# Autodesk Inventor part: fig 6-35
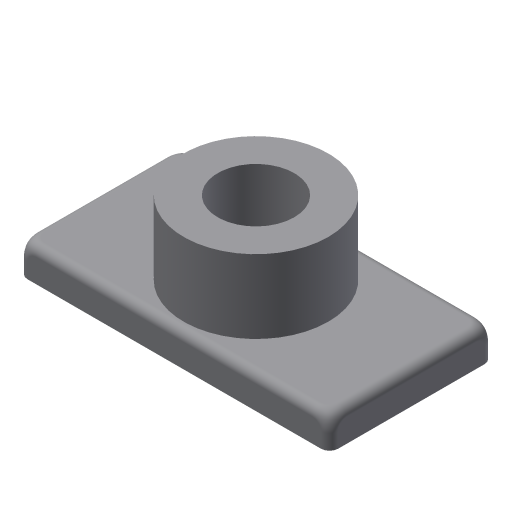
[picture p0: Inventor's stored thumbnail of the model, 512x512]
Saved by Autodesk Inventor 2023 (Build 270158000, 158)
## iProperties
Created: 2004-05
Part Number: fig 6-35
Document SubType Name: Modeling
Designer: CADCIM Technologies
Manufacturer: Standard
Standards Organization: Custom
Density: 1 g/cm^3
Material: Generic
Appearance: Default
Author: CADCIM Technologies
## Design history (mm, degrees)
sketch "Sketch1"
  geometry: L1 (-39.276, -18.692)-(33.721, -18.692); L2 (33.721, -18.692)-(33.721, 19.728); L3 (33.721, 19.728)-(-39.276, 19.728); L4 (-39.276, 19.728)-(-39.276, -18.692)
  constraints: 8 end point, 2 parallel, 1 horizontal, 1 perpendicular
extrude "Extrusion1" new body sketch "Sketch1" distance "d0" = 7.5; taper "d1" = 0 deg
sketch "Sketch2"
  geometry: C1 r 17 at (-2.778, 0.518)
  constraints: 1 centre point
  dimensions: "d16" = 34 diameter of C1
extrude "Extrusion2" join sketch "Sketch2" distance "d3" = 17.25; taper "d4" = 0 deg
hole "Hole1" diameter "d8" = 18; stored, may be unused: countersink angle "d12" = 90 deg, drill point angle "d14" = 118 deg; dims "d6" = 10, "d7" = 10, "d9" = 6, "d10" = 4, "d11" = 2, "d13" = 8
fillet "Fillet4" dims "d17" = 2
body "Solid1"
